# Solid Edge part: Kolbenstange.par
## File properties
Username: bmolnar
Dokumentum tartalom típus: 0
Author: bmolnar
Last saved by: bmolnar
Revision: 92
Sűrűség: 0,000 kg/m^3
Pontosság: 0,990
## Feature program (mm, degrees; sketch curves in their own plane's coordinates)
base feature "unnamed BaseFeature 1"
sketch for "unnamed Protrusion 1" plane through (0, 0, -26) normal (0, 0, -1) x-axis (-1, 0, 0)
  circle centre (0, 0) radius 31.5
extrude "unnamed Protrusion 1" add finite 18.25 along +normal
sketch for "Kihúzás_2" plane through (0, 0, -26) normal (0, 0, -1) x-axis (-1, 0, 0)
  circle centre (0, 0) radius 31.5
extrude "Kihúzás_2" add finite 3.25 along -normal
thread "unnamed Thread 1"
chamfer "Letörés_1" setback 2.75  SetBackValue2 = 20 deg
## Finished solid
Body 1: solid body, 17 faces, 23 edges, 8 vertices.
  Faces by surface: plane 8, cylinder 4, torus 3, cone 2
  Edges by curve: circle 13, line 6, ellipse 2, intersection 2
Bounding box of the edges (mm; curved faces can reach further): 63.000 x 63.000 x 190.250, from (-31.5, -31.5, -44.25) to (31.5, 31.5, 146).
Cylindrical faces by radius (mm): R5 x1, R6 x1, R8 x1, R31.5 x1
Conical faces (half-angle, radius in mm at the cone's reference point): 20 deg R4.9991 x1, 60 deg R5.6 x1
Toroidal faces (ring radius, tube radius in mm): R5.4 r0.4 x2, R6.3 r1.7 x1
Planar faces by outward normal: +x 1, +z 3, -x 1, -z 1, oblique 2
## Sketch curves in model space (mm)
circle centre (0, 0, -26) radius 31.5
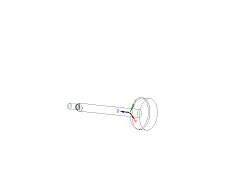
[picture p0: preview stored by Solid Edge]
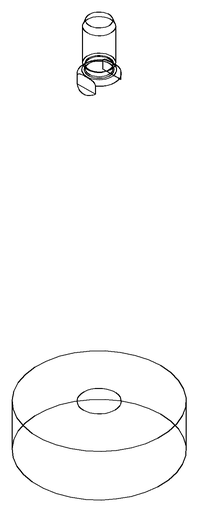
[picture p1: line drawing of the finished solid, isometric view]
